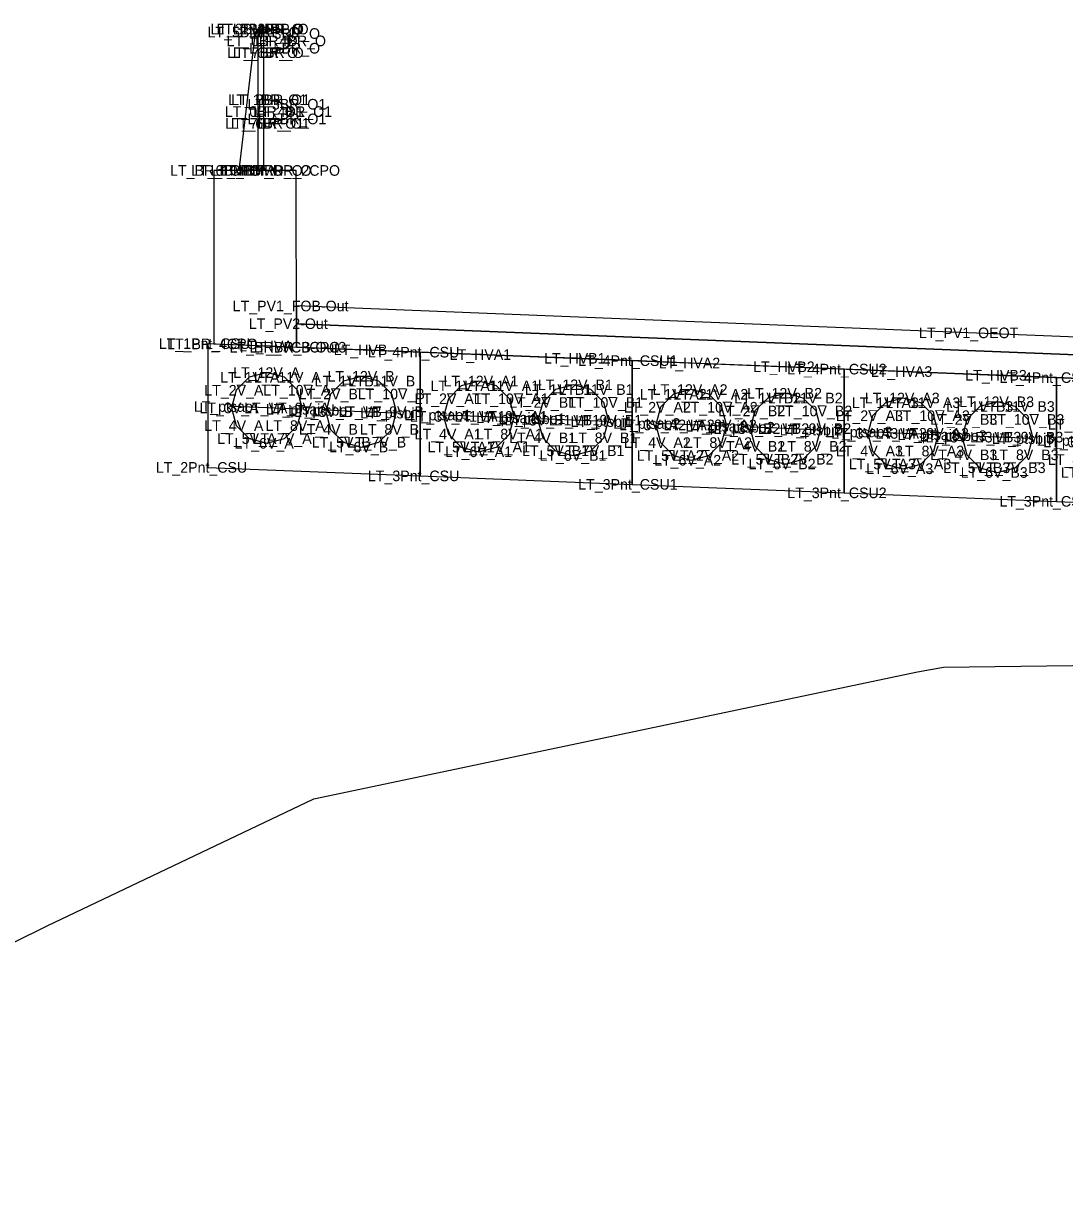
# Model space of a CAD drawing. Extents: x -26 to 1163, y -10 to 9537.
# Drawn here: x 57.64 to 72.36, y 5507.61 to 5524.32 of the extents above; entities that cross this region are included whole.
import ezdxf

# ---------------------------------------------------------------- set-up
doc = ezdxf.new("R2010")
doc.units = 0
for name, color, linetype in [('Exist XS Ground Line', 7, 'Continuous'), ('Prop CMT Bridge Metal Rail', 7, 'Continuous'), ('Prop CMT Bridge Metal Rail Post', 7, 'Continuous'), ('Prop CMT Concrete Structures', 7, 'Continuous'), ('Prop CMT Corridor Surface Symbology Blue', 7, 'Continuous'), ('Prop CMT Pvmt Course 1', 7, 'Continuous'), ('Prop CMT Pvmt Course 2', 7, 'Continuous'), ('Scratch_Level_0', 7, 'Continuous')]:
    doc.layers.add(name, color=color, linetype=linetype)

msp = doc.modelspace()

# ---------------------------------------------------------------- linework, layer by layer
at = {"layer": 'Exist XS Ground Line'}
msp.add_lwpolyline([(50.408, 5507.818), (57.975, 5511.563), (61.745, 5513.361), (70.287, 5515.157), (70.652, 5515.222), (76.125, 5515.292), (80, 5515.342), (82.665, 5515.377), (85.409, 5515.26), (94.805, 5514.85), (98.043, 5514.258), (104.757, 5511.598), (113.21, 5508.172), (121.817, 5507.493), (125.269, 5507.214), (127.758, 5507.11), (137.804, 5508.533), (143.24, 5508.791), (148.098, 5507.061), (150.039, 5505.923), (155.893, 5501.246), (156.599, 5500.79), (160, 5500.863)], dxfattribs=at)
at = {"layer": 'Prop CMT Bridge Metal Rail'}
for points in [[(61.041, 5524.247), (61.124, 5524.247), (61.353, 5524.184), (61.437, 5524.08)], [(61.041, 5524.08), (61.041, 5524.247)], [(61.437, 5524.08), (61.353, 5523.976), (61.124, 5523.913), (61.041, 5523.913)], [(61.041, 5523.913), (61.041, 5524.08)], [(61.041, 5523.247), (61.124, 5523.247), (61.353, 5523.184), (61.437, 5523.08)], [(61.041, 5523.08), (61.041, 5523.247)], [(61.437, 5523.08), (61.353, 5522.976), (61.124, 5522.913), (61.041, 5522.913)], [(61.041, 5522.913), (61.041, 5523.08)]]:
    msp.add_lwpolyline(points, dxfattribs=at)
at = {"layer": 'Prop CMT Bridge Metal Rail Post'}
for points in [[(60.957, 5524.247), (60.916, 5524.205), (60.687, 5522.247)], [(61.041, 5524.247), (60.957, 5524.247)], [(60.957, 5524.247), (60.957, 5522.247)], [(61.041, 5522.247), (61.041, 5524.247)]]:
    msp.add_lwpolyline(points, dxfattribs=at)
at = {"layer": 'Prop CMT Concrete Structures'}
for points in [[(61.5, 5519.747), (61.499, 5522.247), (60.334, 5522.247), (60.333, 5519.793)], [(63.25, 5519.677), (62.417, 5519.71), (61.083, 5519.763), (60.25, 5519.797)], [(60.25, 5519.797), (60.25, 5518.047)], [(60.333, 5519.793), (61.5, 5519.747)], [(66.25, 5519.557), (65.417, 5519.59), (64.083, 5519.643), (63.25, 5519.677)], [(63.25, 5519.677), (63.25, 5517.927)], [(63.25, 5517.927), (63.25, 5519.677)], [(69.25, 5519.437), (68.417, 5519.47), (67.083, 5519.523), (66.25, 5519.557)], [(66.25, 5519.557), (66.25, 5517.807)], [(66.25, 5517.807), (66.25, 5519.557)], [(61.083, 5519.388), (60.833, 5519.321), (60.65, 5519.138), (60.583, 5518.888)], [(61.583, 5518.888), (61.516, 5519.138), (61.333, 5519.321), (61.083, 5519.388)], [(72.25, 5519.317), (71.417, 5519.35), (70.083, 5519.403), (69.25, 5519.437)], [(69.25, 5519.437), (69.25, 5517.687)], [(69.25, 5517.687), (69.25, 5519.437)], [(62.417, 5519.335), (62.167, 5519.268), (61.984, 5519.085), (61.917, 5518.835)], [(62.917, 5518.835), (62.85, 5519.085), (62.667, 5519.268), (62.417, 5519.335)], [(64.083, 5519.268), (63.833, 5519.201), (63.65, 5519.018), (63.583, 5518.768)], [(64.583, 5518.768), (64.516, 5519.018), (64.333, 5519.201), (64.083, 5519.268)], [(75.25, 5519.197), (74.417, 5519.23), (73.083, 5519.283), (72.25, 5519.317)], [(72.25, 5519.317), (72.25, 5517.567)], [(72.25, 5517.567), (72.25, 5519.317)], [(65.417, 5519.215), (65.167, 5519.148), (64.984, 5518.965), (64.917, 5518.715)], [(65.917, 5518.715), (65.85, 5518.965), (65.667, 5519.148), (65.417, 5519.215)], [(67.083, 5519.148), (66.833, 5519.081), (66.65, 5518.898), (66.583, 5518.648)], [(67.583, 5518.648), (67.516, 5518.898), (67.333, 5519.081), (67.083, 5519.148)], [(68.417, 5519.095), (68.167, 5519.028), (67.984, 5518.845), (67.917, 5518.595)], [(68.917, 5518.595), (68.85, 5518.845), (68.667, 5519.028), (68.417, 5519.095)], [(60.583, 5518.888), (60.65, 5518.638), (60.833, 5518.455), (61.083, 5518.388), (61.333, 5518.455), (61.516, 5518.638), (61.583, 5518.888)], [(70.083, 5519.028), (69.833, 5518.961), (69.65, 5518.778), (69.583, 5518.528)], [(70.583, 5518.528), (70.516, 5518.778), (70.333, 5518.961), (70.083, 5519.028)], [(71.417, 5518.975), (71.167, 5518.908), (70.984, 5518.725), (70.917, 5518.475)], [(71.917, 5518.475), (71.85, 5518.725), (71.667, 5518.908), (71.417, 5518.975)], [(61.917, 5518.835), (61.984, 5518.585), (62.167, 5518.402), (62.417, 5518.335), (62.667, 5518.402), (62.85, 5518.585), (62.917, 5518.835)], [(63.583, 5518.768), (63.65, 5518.518), (63.833, 5518.335), (64.083, 5518.268), (64.333, 5518.335), (64.516, 5518.518), (64.583, 5518.768)], [(64.917, 5518.715), (64.984, 5518.465), (65.167, 5518.282), (65.417, 5518.215), (65.667, 5518.282), (65.85, 5518.465), (65.917, 5518.715)], [(66.583, 5518.648), (66.65, 5518.398), (66.833, 5518.215), (67.083, 5518.148), (67.333, 5518.215), (67.516, 5518.398), (67.583, 5518.648)], [(67.917, 5518.595), (67.984, 5518.345), (68.167, 5518.162), (68.417, 5518.095), (68.667, 5518.162), (68.85, 5518.345), (68.917, 5518.595)], [(69.583, 5518.528), (69.65, 5518.278), (69.833, 5518.095), (70.083, 5518.028), (70.333, 5518.095), (70.516, 5518.278), (70.583, 5518.528)], [(70.917, 5518.475), (70.984, 5518.225), (71.167, 5518.042), (71.417, 5517.975), (71.667, 5518.042), (71.85, 5518.225), (71.917, 5518.475)], [(60.25, 5518.047), (63.25, 5517.927)], [(63.25, 5517.927), (66.25, 5517.807)], [(66.25, 5517.807), (69.25, 5517.687)], [(69.25, 5517.687), (72.25, 5517.567)], [(72.25, 5517.567), (75.25, 5517.447)]]:
    msp.add_lwpolyline(points, dxfattribs=at)
at = {"layer": 'Prop CMT Corridor Surface Symbology Blue'}
for points in [[(61.573, 5518.869), (61.083, 5518.888), (60.593, 5518.908)], [(62.907, 5518.815), (62.417, 5518.835), (61.927, 5518.855)], [(64.573, 5518.749), (64.083, 5518.768), (63.593, 5518.788)], [(65.907, 5518.695), (65.417, 5518.715), (64.927, 5518.735)], [(67.573, 5518.629), (67.083, 5518.648), (66.593, 5518.668)], [(68.907, 5518.575), (68.417, 5518.595), (67.927, 5518.615)], [(70.573, 5518.509), (70.083, 5518.528), (69.593, 5518.548)], [(71.907, 5518.455), (71.417, 5518.475), (70.927, 5518.495)]]:
    msp.add_lwpolyline(points, dxfattribs=at)
at = {"layer": 'Prop CMT Pvmt Course 1'}
for points in [[(80, 5519.59), (71, 5519.95), (61.5, 5520.33)], [(61.5, 5520.33), (61.5, 5520.08), (80, 5519.34)]]:
    msp.add_lwpolyline(points, dxfattribs=at)
at = {"layer": 'Prop CMT Pvmt Course 2'}
for points in [[(80, 5519.34), (61.5, 5520.08)], [(61.5, 5520.08), (61.5, 5519.747), (80, 5519.007)]]:
    msp.add_lwpolyline(points, dxfattribs=at)

# ---------------------------------------------------------------- texts
at = {"layer": 'Scratch_Level_0'}
for s, p in [('LT_5BMRP_O', (60.244, 5524.13)), ('LT_3BMRP_O', (60.285, 5524.172)), ('LT_2BMRP_O', (60.369, 5524.172)), ('LT_2BR_O', (60.603, 5524.172)), ('LT_3BR_O', (60.832, 5524.109)), ('LT_0BR_O', (60.514, 5524.005)), ('LT_4BR_O', (60.916, 5524.005)), ('LT_7BR_O', (60.52, 5523.838)), ('LT_6BR_O', (60.6, 5523.838)), ('LT_5BR_O', (60.832, 5523.901)), ('LT_1BR_O1', (60.538, 5523.172)), ('LT_2BR_O1', (60.578, 5523.172)), ('LT_3BR_O1', (60.808, 5523.109)), ('LT_0BR_O1', (60.489, 5523.005)), ('LT_4BR_O1', (60.891, 5523.005)), ('LT_7BR_O1', (60.495, 5522.838)), ('LT_6BR_O1', (60.575, 5522.838)), ('LT_5BR_O1', (60.808, 5522.901)), ('LT_BR_1CPO', (59.714, 5522.172)), ('LT_6BMRP_O', (60.011, 5522.172)), ('LT_4BMRP_O', (60.285, 5522.172)), ('LT_1BMRP_O', (60.411, 5522.172)), ('LT_BR_2CPO', (60.836, 5522.172)), ('LT_PV1_FOB-Out', (60.599, 5520.255)), ('LT_PV2-Out', (60.829, 5520.005)), ('LT_PV1_OEOT', (70.306, 5519.875)), ('LT_1Pnt_CSU', (59.554, 5519.722)), ('LT_BR_4CPO', (59.671, 5519.718)), ('LT_BR_VCB-Out3', (60.555, 5519.672)), ('LT_HVA', (60.692, 5519.688)), ('LT_BR_3CPO', (60.837, 5519.672)), ('LT_HVB', (62.028, 5519.635)), ('LT_4Pnt_CSU', (62.512, 5519.602)), ('LT_HVA1', (63.668, 5519.568)), ('LT_HVB1', (65.003, 5519.515)), ('LT_4Pnt_CSU1', (65.487, 5519.482)), ('LT_HVA2', (66.625, 5519.448)), ('LT_1V_A', (60.423, 5519.246)), ('LT_12V_A', (60.606, 5519.313)), ('LT_11V_A', (60.899, 5519.246)), ('LT_12V_B', (61.942, 5519.26)), ('LT_HVB2', (67.961, 5519.395)), ('LT_4Pnt_CSU2', (68.444, 5519.362)), ('LT_HVA3', (69.625, 5519.328)), ('LT_HVB3', (70.961, 5519.275)), ('LT_4Pnt_CSU3', (71.444, 5519.242)), ('LT_1V_B', (61.759, 5519.193)), ('LT_11V_B', (62.234, 5519.193)), ('LT_1V_A1', (63.399, 5519.126)), ('LT_12V_A1', (63.581, 5519.193)), ('LT_11V_A1', (63.874, 5519.126)), ('LT_1V_B1', (64.734, 5519.073)), ('LT_12V_B1', (64.917, 5519.14)), ('LT_11V_B1', (65.21, 5519.073)), ('LT_12V_A2', (66.539, 5519.073)), ('LT_2V_A', (60.198, 5519.063)), ('LT_10V_A', (61.033, 5519.063)), ('LT_2V_B', (61.534, 5519.01)), ('LT_10V_B', (62.369, 5519.01)), ('LT_2V_A1', (63.173, 5518.943)), ('LT_10V_A1', (64.008, 5518.943)), ('LT_1V_A2', (66.356, 5519.006)), ('LT_11V_A2', (66.831, 5519.006)), ('LT_1V_B2', (67.692, 5518.953)), ('LT_12V_B2', (67.875, 5519.02)), ('LT_11V_B2', (68.167, 5518.953)), ('LT_12V_A3', (69.539, 5518.953)), ('LT_12V_B3', (70.875, 5518.9)), ('LT_ptsao', (60.049, 5518.833)), ('LT_3V_A', (60.131, 5518.813)), ('LT_VA', (60.76, 5518.813)), ('LT_ptsai', (61.069, 5518.794)), ('LT_9V_A', (61.131, 5518.813)), ('LT_ptsbo', (61.383, 5518.78)), ('LT_3V_B', (61.467, 5518.76)), ('LT_VB', (62.095, 5518.76)), ('LT_ptsbi', (62.404, 5518.74)), ('LT_9V_B', (62.467, 5518.76)), ('LT_2V_B1', (64.509, 5518.89)), ('LT_10V_B1', (65.344, 5518.89)), ('LT_2V_A2', (66.131, 5518.823)), ('LT_10V_A2', (66.966, 5518.823)), ('LT_2V_B2', (67.466, 5518.77)), ('LT_10V_B2', (68.302, 5518.77)), ('LT_1V_A3', (69.356, 5518.886)), ('LT_11V_A3', (69.831, 5518.886)), ('LT_1V_B3', (70.692, 5518.833)), ('LT_11V_B3', (71.167, 5518.833)), ('LT_ptsao1', (63.024, 5518.713)), ('LT_3V_A1', (63.106, 5518.693)), ('LT_VA1', (63.735, 5518.693)), ('LT_ptsai1', (64.044, 5518.674)), ('LT_9V_A1', (64.106, 5518.693)), ('LT_ptsbo1', (64.359, 5518.66)), ('LT_3V_B1', (64.442, 5518.64)), ('LT_VB1', (65.071, 5518.64)), ('LT_ptsbi1', (65.379, 5518.62)), ('LT_9V_B1', (65.442, 5518.64)), ('LT_ptsao2', (65.982, 5518.593)), ('LT_3V_A2', (66.064, 5518.573)), ('LT_VA2', (66.692, 5518.573)), ('LT_9V_A2', (67.064, 5518.573)), ('LT_2V_A3', (69.131, 5518.703)), ('LT_10V_A3', (69.966, 5518.703)), ('LT_2V_B3', (70.466, 5518.65)), ('LT_10V_B3', (71.302, 5518.65)), ('LT_2V_A4', (72.131, 5518.583)), ('LT_4V_A', (60.198, 5518.563)), ('LT_8V_A', (61.064, 5518.563)), ('LT_4V_B', (61.534, 5518.51)), ('LT_8V_B', (62.4, 5518.51)), ('LT_4V_A1', (63.173, 5518.443)), ('LT_8V_A1', (64.039, 5518.443)), ('LT_ptsai2', (67.002, 5518.554)), ('LT_ptsbo2', (67.316, 5518.54)), ('LT_3V_B2', (67.399, 5518.52)), ('LT_VB2', (68.028, 5518.52)), ('LT_ptsbi2', (68.336, 5518.5)), ('LT_9V_B2', (68.399, 5518.52)), ('LT_ptsao3', (68.982, 5518.473)), ('LT_3V_A3', (69.064, 5518.453)), ('LT_VA3', (69.692, 5518.453)), ('LT_ptsai3', (70.002, 5518.434)), ('LT_9V_A3', (70.064, 5518.453)), ('LT_ptsbo3', (70.316, 5518.42)), ('LT_3V_B3', (70.399, 5518.4)), ('LT_VB3', (71.028, 5518.4)), ('LT_9V_B3', (71.399, 5518.4)), ('LT_5V_A', (60.381, 5518.38)), ('LT_6V_A', (60.627, 5518.313)), ('LT_7V_A', (60.881, 5518.38)), ('LT_5V_B', (61.717, 5518.327)), ('LT_6V_B', (61.963, 5518.26)), ('LT_7V_B', (62.217, 5518.327)), ('LT_5V_A1', (63.356, 5518.26)), ('LT_7V_A1', (63.856, 5518.26)), ('LT_4V_B1', (64.509, 5518.39)), ('LT_8V_B1', (65.375, 5518.39)), ('LT_4V_A2', (66.131, 5518.323)), ('LT_8V_A2', (66.997, 5518.323)), ('LT_4V_B2', (67.466, 5518.27)), ('LT_8V_B2', (68.332, 5518.27)), ('LT_ptsbi3', (71.336, 5518.38)), ('LT_ptsao4', (71.982, 5518.353)), ('LT_3V_A4', (72.064, 5518.333)), ('LT_6V_A1', (63.603, 5518.193)), ('LT_5V_B1', (64.692, 5518.207)), ('LT_6V_B1', (64.938, 5518.14)), ('LT_7V_B1', (65.192, 5518.207)), ('LT_5V_A2', (66.314, 5518.14)), ('LT_6V_A2', (66.56, 5518.073)), ('LT_7V_A2', (66.814, 5518.14)), ('LT_5V_B2', (67.649, 5518.087)), ('LT_7V_B2', (68.149, 5518.087)), ('LT_4V_A3', (69.131, 5518.203)), ('LT_8V_A3', (69.997, 5518.203)), ('LT_4V_B3', (70.466, 5518.15)), ('LT_8V_B3', (71.332, 5518.15)), ('LT_4V_A4', (72.131, 5518.083)), ('LT_2Pnt_CSU', (59.512, 5517.972)), ('LT_6V_B2', (67.896, 5518.02)), ('LT_5V_A3', (69.314, 5518.02)), ('LT_6V_A3', (69.56, 5517.953)), ('LT_7V_A3', (69.814, 5518.02)), ('LT_5V_B3', (70.649, 5517.967)), ('LT_6V_B3', (70.896, 5517.9)), ('LT_7V_B3', (71.149, 5517.967)), ('LT_5V_A4', (72.314, 5517.9)), ('LT_3Pnt_CSU', (62.512, 5517.852)), ('LT_3Pnt_CSU1', (65.487, 5517.732)), ('LT_3Pnt_CSU2', (68.444, 5517.612)), ('LT_3Pnt_CSU3', (71.444, 5517.492))]:
    msp.add_text(s, height=0.15, dxfattribs=at).set_placement(p)

doc.saveas('drawing.dxf')
